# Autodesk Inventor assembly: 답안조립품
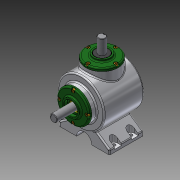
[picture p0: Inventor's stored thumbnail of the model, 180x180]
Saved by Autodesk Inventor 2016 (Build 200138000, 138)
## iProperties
Created: 2017-04
Part Number: 답안조립품
Material: 일반
Document SubType Name: Assembly
Designer: CAMTIC
Author: CAMTIC
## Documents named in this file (14)
- C:\Users\CAMTIC\Desktop\470407V1022\답안조립품.iam
- C:\Users\CAMTIC\Desktop\470407V1022\1-본체.ipt
- C:\Users\CAMTIC\Desktop\470407V1022\메인 베벨기어.ipt
- C:\Users\CAMTIC\Desktop\470407V1022\메인 축.ipt
- 메인 축.ipt
- C:\Users\CAMTIC\Desktop\470407V1022\베어링 6203.ipt
- C:\Users\CAMTIC\Desktop\470407V1022\볼트 M4.ipt
- C:\Users\CAMTIC\Desktop\470407V1022\서브 베벨기어.ipt
- C:\Users\CAMTIC\Desktop\470407V1022\서브 축.ipt
- 서브 축.ipt
- C:\Users\CAMTIC\Desktop\470407V1022\오일실 17 32 8.ipt
- C:\Users\CAMTIC\Desktop\470407V1022\커버.ipt
- C:\Users\CAMTIC\Desktop\470407V1022\키 4x4.ipt
- C:\Users\CAMTIC\Desktop\470407V1022\키 5x5.ipt
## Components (1 placed, 1 different names)
1. 1-본체:1
